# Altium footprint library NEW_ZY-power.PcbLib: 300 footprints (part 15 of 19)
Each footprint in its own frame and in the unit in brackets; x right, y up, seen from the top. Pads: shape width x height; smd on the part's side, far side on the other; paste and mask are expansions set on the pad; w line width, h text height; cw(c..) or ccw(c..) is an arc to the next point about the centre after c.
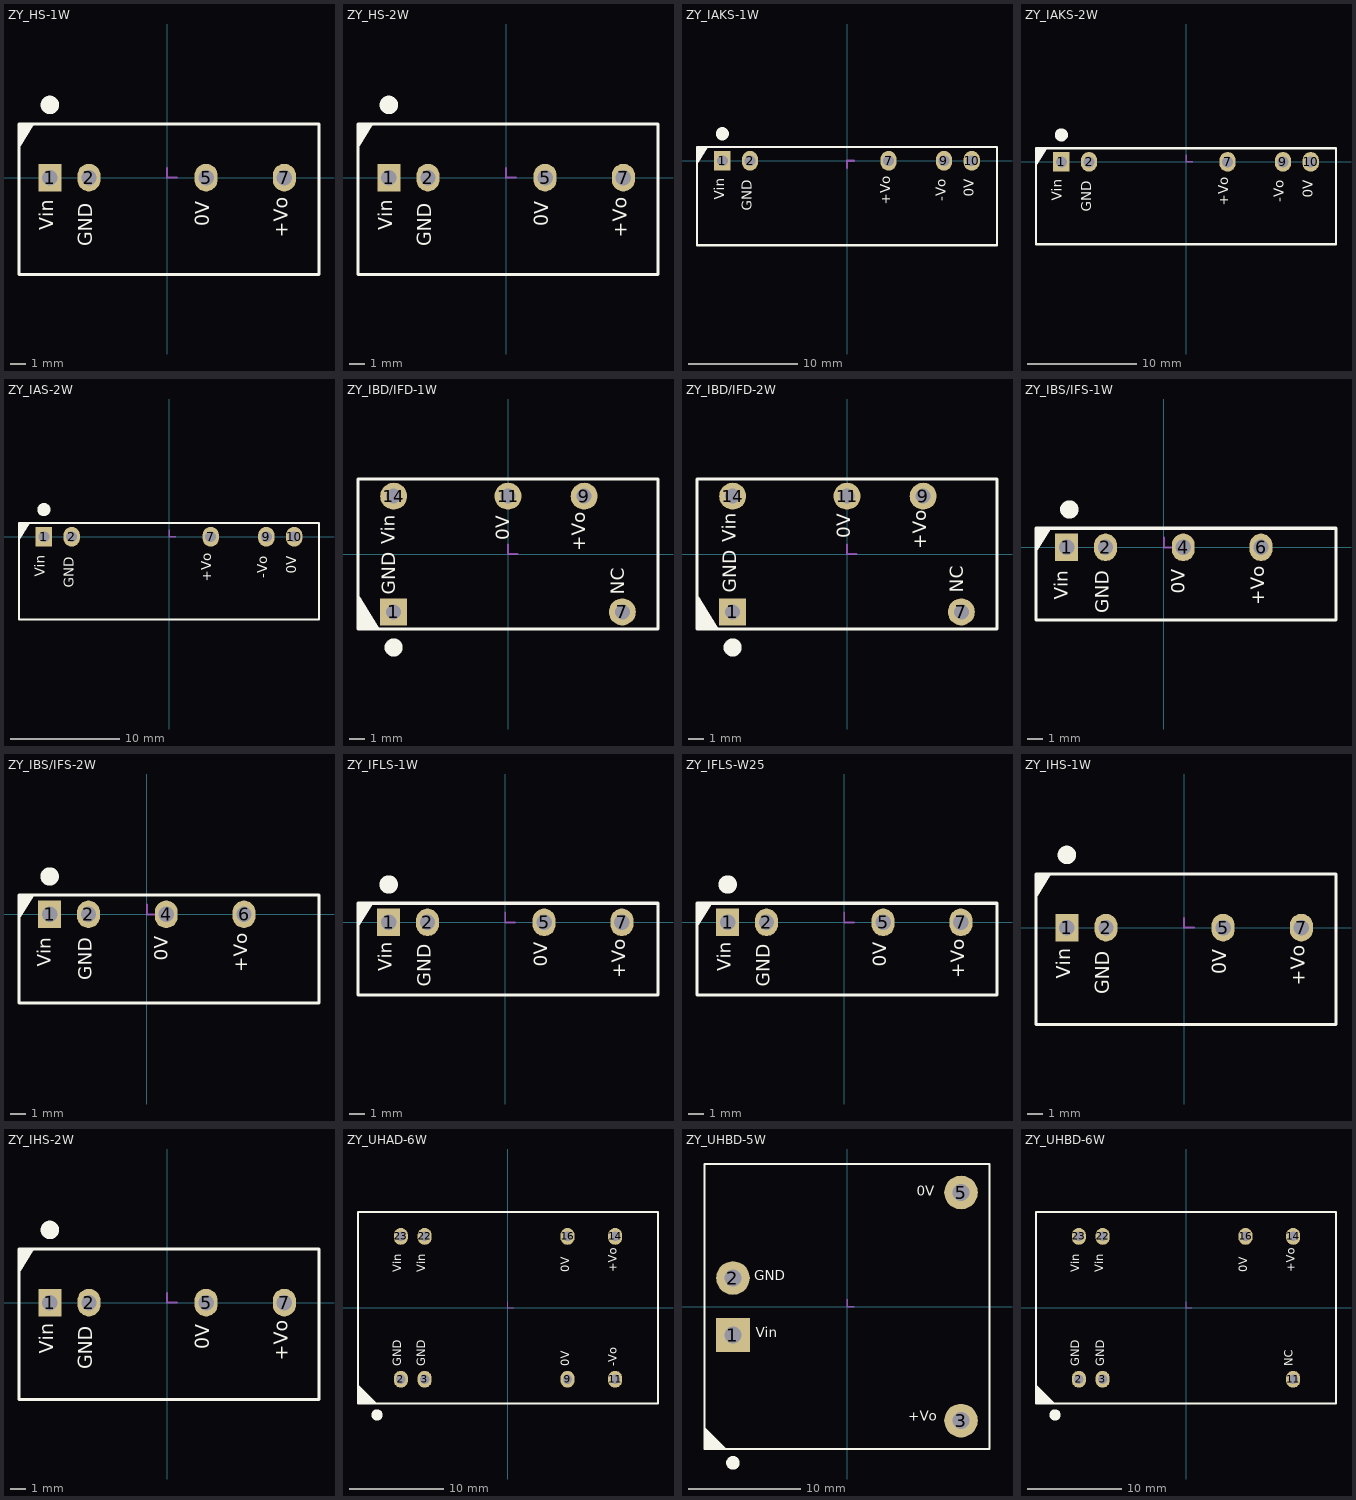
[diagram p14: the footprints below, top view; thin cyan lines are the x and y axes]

## ZY_HS-1W [mm]
pads (4):
  rect 1.5x1.8 hole 1: 1(-7.62,0)
  oval 1.5x1.8 hole 1: 2(-5.08,0) 5(2.533,0) 7(7.62,0)
Top Overlay:
  circle w1: c-7.62,4.725 r0.1
  region: -9.62,1.914 -9.62,3.5 -8.626,3.5
  lines w0.2: 9.873,3.45 9.873,-6.3 -9.627,-6.3 -9.627,3.5 9.873,3.5
  text "+Vo" at 8.128,-3.903 h1.52
  text "0V" at 3.048,-3.163 h1.52
  text "GND" at -4.572,-4.445 h1.52
  text "Vin" at -7.112,-3.435 h1.52
Mechanical 15:
  lines w0.127: 0,0.635 0,0 0.635,0

## ZY_HS-2W [mm]
pads (4):
  rect 1.5x1.8 hole 1: 1(-7.62,0)
  oval 1.5x1.8 hole 1: 2(-5.08,0) 5(2.533,0) 7(7.62,0)
Top Overlay:
  circle w1: c-7.62,4.725 r0.1
  region: -9.62,1.914 -9.62,3.5 -8.626,3.5
  lines w0.2: 9.873,3.45 9.873,-6.3 -9.627,-6.3 -9.627,3.5 9.873,3.5
  text "Vin" at -7.112,-3.435 h1.52
  text "GND" at -4.572,-4.445 h1.52
  text "0V" at 3.048,-3.163 h1.52
  text "+Vo" at 8.128,-3.903 h1.52
Mechanical 15:
  lines w0.127: 0,0.635 0,0 0.635,0

## ZY_IAKS-1W [mm] "定压输入隔离稳压双输出"
height 11.5
pads (5):
  rect 1.5x1.8 hole 1: 1(-11.43,0)
  oval 1.5x1.8 hole 1: 2(-8.89,0) 7(3.81,0) 9(8.89,0) 10(11.43,0)
Top Overlay:
  circle w1: c-11.43,2.475 r0.1
  region: -13.75,-0.336 -13.75,1.25 -12.756,1.25
  lines w0.2: -13.75,-7.75 13.75,-7.75 13.75,1.25 -13.75,1.25 -13.75,-7.75
  text "Vin" at -10.935,-3.562 h1.52
  text "GND" at -8.395,-4.572 h1.52
  text "+Vo" at 4.305,-4.03 h1.52
  text "-Vo" at 9.385,-3.718 h1.52
  text "0V" at 11.925,-3.29 h1.52
Mechanical 15:
  lines w0.203: 0,-0.635 0,0 0.635,0

## ZY_IAKS-2W [mm]
pads (5):
  rect 1.5x1.8 hole 1: 1(-11.43,0)
  oval 1.5x1.8 hole 1: 2(-8.89,0) 7(3.81,0) 9(8.89,0) 10(11.43,0)
Top Overlay:
  circle w1: c-11.43,2.475 r0.1
  region: -13.732,-0.336 -13.732,1.25 -12.738,1.25
  lines w0.2: -13.75,1.232 -13.75,-7.55 13.75,-7.55 13.75,1.25 -13.732,1.25
  text "Vin" at -11.049,-3.562 h1.52
  text "GND" at -8.382,-4.572 h1.52
  text "+Vo" at 4.191,-4.03 h1.52
  text "-Vo" at 9.271,-3.718 h1.52
  text "0V" at 11.938,-3.29 h1.52
Mechanical 15:
  lines w0.127: 0,0.635 0,0 0.635,0

## ZY_IAS-2W [mm]
height 10.1
pads (5):
  rect 1.5x1.8 hole 1: 1(-11.43,0)
  oval 1.5x1.8 hole 1: 2(-8.89,0) 7(3.81,0) 9(8.89,0) 10(11.43,0)
Top Overlay:
  circle w1: c-11.43,2.475 r0.1
  region: -13.7,-0.336 -13.7,1.25 -12.706,1.25
  lines w0.2: -13.7,-7.55 -13.7,1.25 13.7,1.25 13.7,-7.55 -13.7,-7.55
  text "0V" at 11.938,-3.375 h1.52
  text "-Vo" at 9.271,-3.802 h1.52
  text "+Vo" at 4.191,-4.115 h1.52
  text "GND" at -8.382,-4.657 h1.52
  text "Vin" at -11.049,-3.646 h1.52
Mechanical 15:
  lines w0.127: 0,0.635 0,0 0.635,0

## ZY_IBD/IFD-1W [mm]
height 8.1
pads (5):
  rect 1.8x1.8 hole 1: 1(-7.62,-3.86)
  round 1.8 hole 1: 7(7.62,-3.86) 9(5.08,3.86) 11(0,3.86) 14(-7.62,3.86)
Top Overlay:
  circle w1: c-7.62,-6.225 r0.1
  region: -10,-2.67 -10,-5 -8.54,-5
  lines w0.2: -10,-5 10,-5 10,5 -10,5 -10,-5
  text "GND" at -7.206,-2.714 h1.52
  text "NC" at 8.034,-2.714 h1.52
  text "+Vo" at 5.461,0.18 h1.52
  text "0V" at 0.381,0.92 h1.52
  text "Vin" at -7.239,0.648 h1.52
Mechanical 15:
  lines w0.127: 0,0.635 0,0 0.635,0

## ZY_IBD/IFD-2W [mm]
pads (5):
  rect 1.8x1.8 hole 1: 1(-7.62,-3.86)
  round 1.8 hole 1: 7(7.62,-3.86) 9(5.08,3.86) 11(0,3.86) 14(-7.62,3.86)
Top Overlay:
  circle w1: c-7.62,-6.225 r0.1
  region: -10,-2.67 -10,-5 -8.54,-5
  lines w0.2: -10,-5 -10,5 10,5 10,-5 -10,-5
  text "Vin" at -7.112,0.775 h1.52
  text "0V" at 0.508,1.047 h1.52
  text "+Vo" at 5.588,0.307 h1.52
  text "NC" at 8.034,-2.587 h1.52
  text "GND" at -7.079,-2.587 h1.52
Mechanical 15:
  lines w0.127: 0,0.635 0,0 0.635,0

## ZY_IBS/IFS-1W [mm] "定压输入隔离稳压单输出"
height 10
pads (4):
  rect 1.5x1.8 hole 1: 1(-6.35,0)
  oval 1.5x1.8 hole 1: 2(-3.81,0) 4(1.27,0) 6(6.35,0)
Top Overlay:
  circle w1: c-6.17,2.475 r0.1
  region: -8.35,-0.336 -8.35,1.25 -7.356,1.25
  lines w0.2: -8.35,-4.75 11.25,-4.75 11.25,1.25 -8.35,1.25 -8.35,-4.75
  text "Vin" at -5.969,-3.435 h1.52
  text "GND" at -3.302,-4.318 h1.52
  text "0V" at 1.651,-3.036 h1.52
  text "+Vo" at 6.858,-3.776 h1.52
Mechanical 15:
  lines w0.127: 0,0.635 0,0 0.635,0

## ZY_IBS/IFS-2W [mm]
pads (4):
  rect 1.5x1.8 hole 1: 1(-6.35,0)
  oval 1.5x1.8 hole 1: 2(-3.81,0) 4(1.27,0) 6(6.35,0)
Top Overlay:
  circle w1: c-6.35,2.475 r0.1
  region: -8.35,-0.336 -8.35,1.25 -7.356,1.25
  lines w0.2: -8.35,-5.8 11.25,-5.8 11.25,1.25 -8.35,1.25 -8.35,-5.8
  text "Vin" at -5.969,-3.435 h1.52
  text "GND" at -3.302,-4.318 h1.52
  text "0V" at 1.651,-3.036 h1.52
  text "+Vo" at 6.858,-3.776 h1.52
Mechanical 15:
  lines w0.127: 0,0.635 0,0 0.635,0

## ZY_IFLS-1W [mm]
pads (4):
  rect 1.5x1.8 hole 1: 1(-7.62,0)
  oval 1.5x1.8 hole 1: 2(-5.08,0) 5(2.54,0) 7(7.62,0)
Top Overlay:
  circle w1: c-7.62,2.475 r0.1
  region: -9.62,-0.336 -9.62,1.25 -8.626,1.25
  lines w0.2: -9.62,-4.75 -9.62,1.25 9.98,1.25 9.98,-4.75 -9.62,-4.75
  text "+Vo" at 8.128,-3.649 h1.52
  text "0V" at 3.048,-2.909 h1.52
  text "GND" at -4.572,-4.191 h1.52
  text "Vin" at -7.112,-3.181 h1.52
Mechanical 15:
  lines w0.127: 0,0.635 0,0 0.635,0

## ZY_IFLS-W25 [mm]
pads (4):
  rect 1.5x1.8 hole 1: 1(-7.62,0)
  oval 1.5x1.8 hole 1: 2(-5.08,0) 5(2.54,0) 7(7.62,0)
Top Overlay:
  circle w1: c-7.62,2.475 r0.1
  region: -9.62,-0.336 -9.62,1.25 -8.626,1.25
  lines w0.2: -9.62,-4.75 9.98,-4.75 9.98,1.25 -9.62,1.25 -9.62,-4.75
  text "+Vo" at 8.128,-3.649 h1.52
  text "0V" at 3.048,-2.909 h1.52
  text "GND" at -4.572,-4.191 h1.52
  text "Vin" at -7.112,-3.181 h1.52
Mechanical 15:
  lines w0.127: 0,0.635 0,0 0.635,0

## ZY_IHS-1W [mm]
height 12.5
pads (4):
  rect 1.5x1.8 hole 1: 1(-7.62,0)
  oval 1.5x1.8 hole 1: 2(-5.08,0) 5(2.533,0) 7(7.62,0)
Top Overlay:
  circle w1: c-7.62,4.725 r0.1
  region: -9.62,1.914 -9.62,3.5 -8.626,3.5
  lines w0.2: 9.873,3.45 9.873,-6.3 -9.627,-6.3 -9.627,3.5 9.873,3.5
  text "+Vo" at 8.128,-3.776 h1.52
  text "0V" at 3.048,-3.036 h1.52
  text "GND" at -4.572,-4.318 h1.52
  text "Vin" at -7.112,-3.308 h1.52
Mechanical 15:
  lines w0.127: 0,0.635 0,0 0.635,0

## ZY_IHS-2W [mm]
height 12.5
pads (4):
  rect 1.5x1.8 hole 1: 1(-7.62,0)
  oval 1.5x1.8 hole 1: 2(-5.08,0) 5(2.533,0) 7(7.62,0)
Top Overlay:
  circle w1: c-7.62,4.725 r0.1
  region: -9.62,1.914 -9.62,3.5 -8.626,3.5
  lines w0.2: 9.873,3.45 9.873,-6.3 -9.627,-6.3 -9.627,3.5 9.873,3.5
  text "Vin" at -7.112,-3.308 h1.52
  text "GND" at -4.572,-4.318 h1.52
  text "0V" at 3.048,-3.036 h1.52
  text "+Vo" at 8.128,-3.776 h1.52
Mechanical 15:
  lines w0.127: 0,0.635 0,0 0.635,0

## ZY_UHAD-6W [mm]
height 10.5
pads (8):
  oval 1.5x1.8 hole 1: 2(-11.43,-7.62) 3(-8.89,-7.62) 9(6.35,-7.62) 11(11.43,-7.62) 14(11.43,7.62) 16(6.35,7.62) 22(-8.89,7.62) 23(-11.43,7.62)
Top Overlay:
  circle w1: c-13.97,-11.425 r0.1
  region: -16,-10.2 -14.025,-10.2 -16,-8.225
  lines w0.2: -16,-10.2 16,-10.2 16,10.2 -16,10.2 -16,-10.2
  text "0V" at 6.858,3.81 h1.52
  text "+Vo" at 11.938,3.81 h1.52
  text "-Vo" at 11.938,-6.223 h1.52
  text "Vin" at -8.509,3.81 h1.52
  text "Vin" at -11.049,3.81 h1.52
  text "GND" at -8.509,-6.223 h1.52
  text "GND" at -11.049,-6.223 h1.52
  text "0V" at 6.858,-6.223 h1.52
Mechanical 15:
  lines w0.127: 0,0.635 0,0 0.635,0

## ZY_UHBD-5W [mm]
height 11.7
pads (4):
  rect 3x3 hole 1.5: 1(-10.16,-2.54)
  round 3 hole 1.5: 2(-10.16,2.54) 3(10.16,-10.16) 5(10.16,10.16)
Top Overlay:
  circle w1: c-10.16,-13.925 r0.1
  region: -12.7,-12.7 -10.725,-12.7 -12.7,-10.725
  lines w0.2: -12.7,-12.7 12.7,-12.7 12.7,12.7 -12.7,12.7 -12.7,-12.7
  text "0V" at 6.201,9.576 h1.52
  text "+Vo" at 5.461,-10.49 h1.52
  text "Vin" at -8.128,-3.048 h1.52
  text "GND" at -8.255,2.032 h1.52
Mechanical 15:
  lines w0.127: 0,0.635 0,0 0.635,0

## ZY_UHBD-6W [mm]
height 10.5
pads (7):
  oval 1.5x1.8 hole 1: 2(-11.43,-7.62) 3(-8.89,-7.62) 11(11.43,-7.62) 14(11.43,7.62) 16(6.35,7.62) 22(-8.89,7.62) 23(-11.43,7.62)
Top Overlay:
  circle w1: c-13.97,-11.425 r0.1
  region: -16,-10.2 -14.025,-10.2 -16,-8.225
  lines w0.2: -16,-10.2 16,-10.2 16,10.2 -16,10.2 -16,-10.2
  text "0V" at 6.858,3.81 h1.52
  text "+Vo" at 11.938,3.81 h1.52
  text "NC" at 11.684,-6.223 h1.52
  text "Vin" at -8.509,3.81 h1.52
  text "Vin" at -11.049,3.81 h1.52
  text "GND" at -8.382,-6.223 h1.52
  text "GND" at -11.049,-6.223 h1.52
Mechanical 15:
  lines w0.127: 0,0.635 0,0 0.635,0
